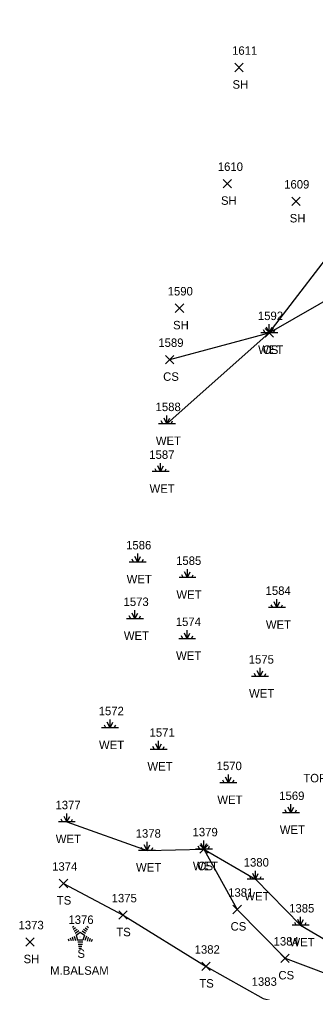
# Model space of a CAD drawing. Extents: x 1554917 to 1555870, y 813367 to 816333.
# Drawn here: x 1555068.3 to 1555138.3, y 813931.9 to 814161.6 of the extents above; entities that cross this region are included whole.
import ezdxf

# ---------------------------------------------------------------- set-up
doc = ezdxf.new("R2010")
doc.units = 0
for name, color, linetype in [('L_A', 7, 'Continuous'), ('L_C', 7, 'Continuous'), ('L_I', 7, 'Continuous'), ('L_TIC', 7, 'Continuous'), ('LELB', 7, 'Continuous'), ('LTC', 7, 'Continuous'), ('LWET', 7, 'Continuous'), ('U_C', 7, 'Continuous')]:
    doc.layers.add(name, color=color, linetype=linetype)

msp = doc.modelspace()

# ---------------------------------------------------------------- linework, layer by layer
at = {"layer": 'L_TIC'}
for points in [[(1555119.17, 814149.25), (1555121.17, 814151.25)], [(1555121.17, 814149.25), (1555119.17, 814151.25)], [(1555116.44, 814121.84), (1555118.44, 814123.84)], [(1555118.44, 814121.84), (1555116.44, 814123.84)], [(1555132.68, 814117.68), (1555134.68, 814119.68)], [(1555134.68, 814117.68), (1555132.68, 814119.68)], [(1555105.12, 814092.44), (1555107.12, 814094.44)], [(1555107.12, 814092.44), (1555105.12, 814094.44)], [(1555126.34, 814086.63), (1555128.34, 814088.63)], [(1555128.34, 814086.63), (1555126.34, 814088.63)], [(1555102.83, 814080.29), (1555104.83, 814082.29)], [(1555104.83, 814080.29), (1555102.83, 814082.29)], [(1555110.92, 813964.76), (1555112.92, 813966.76)], [(1555112.92, 813964.76), (1555110.92, 813966.76)], [(1555077.74, 813956.64), (1555079.74, 813958.64)], [(1555079.74, 813956.64), (1555077.74, 813958.64)], [(1555118.76, 813950.5), (1555120.76, 813952.5)], [(1555120.76, 813950.5), (1555118.76, 813952.5)], [(1555091.79, 813949.17), (1555093.79, 813951.17)], [(1555093.79, 813949.17), (1555091.79, 813951.17)], [(1555069.81, 813942.81), (1555071.81, 813944.81)], [(1555071.81, 813942.81), (1555069.81, 813944.81)], [(1555130.06, 813938.98), (1555132.06, 813940.98)], [(1555132.06, 813938.98), (1555130.06, 813940.98)], [(1555111.4, 813937.05), (1555113.4, 813939.05)], [(1555113.4, 813937.05), (1555111.4, 813939.05)]]:
    msp.add_lwpolyline(points, dxfattribs=at)
at = {"layer": 'LELB'}
for points in [[(1555103.83, 814081.29), (1555127.34, 814087.63), (1555145.8, 814111.67), (1555155.27, 814142.44), (1555178.24, 814154.02), (1555199.22, 814158.86), (1555221.17, 814170.73)], [(1555111.92, 813965.76), (1555119.76, 813951.5), (1555131.06, 813939.98), (1555141.33, 813936.14), (1555158.29, 813940)], [(1555078.74, 813957.64), (1555092.79, 813950.17), (1555112.4, 813938.05), (1555125.87, 813930.47), (1555142.24, 813926.36), (1555153.95, 813930.09)]]:
    msp.add_lwpolyline(points, dxfattribs=at)
at = {"layer": 'LTC'}
for p, q in [((1555080.83, 813947.29), (1555081.18, 813947.55)), ((1555081.04, 813946.83), (1555081.57, 813947.21)), ((1555081.25, 813946.36), (1555081.95, 813946.87)), ((1555081.46, 813945.89), (1555082.34, 813946.53)), ((1555081.68, 813945.44), (1555082.69, 813946.17)), ((1555081.68, 813945.44), (1555082.07, 813944.25)), ((1555082.69, 813946.17), (1555083.69, 813945.45)), ((1555083.11, 813946.49), (1555083.92, 813945.9)), ((1555083.69, 813945.45), (1555083.3, 813944.25)), ((1555083.49, 813946.83), (1555084.16, 813946.34)), ((1555083.86, 813947.18), (1555084.41, 813946.78)), ((1555084.23, 813947.53), (1555084.65, 813947.23)), ((1555079.86, 813944.57), (1555080.01, 813944.1)), ((1555080.32, 813944.79), (1555080.53, 813944.14)), ((1555080.77, 813945), (1555081.04, 813944.17)), ((1555081.23, 813945.22), (1555081.56, 813944.2)), ((1555083.3, 813944.25), (1555082.07, 813944.25)), ((1555083.26, 813943.75), (1555082.12, 813943.75)), ((1555083.18, 813943.25), (1555082.19, 813943.25)), ((1555084.13, 813945.18), (1555083.79, 813944.14)), ((1555084.57, 813944.93), (1555084.29, 813944.04)), ((1555085.02, 813944.68), (1555084.78, 813943.95)), ((1555085.46, 813944.43), (1555085.28, 813943.85)), ((1555083.09, 813942.75), (1555082.26, 813942.75)), ((1555083.01, 813942.25), (1555082.34, 813942.25))]:
    msp.add_line(p, q, dxfattribs=at)
at = {"layer": 'LWET'}
for p, q in [((1555126.34, 814087.63), (1555126.01, 814088.3)), ((1555127.34, 814087.63), (1555126.67, 814088.97)), ((1555127.34, 814087.63), (1555127.34, 814089.63)), ((1555127.34, 814087.63), (1555128.01, 814088.97)), ((1555128.34, 814087.63), (1555128.67, 814088.3)), ((1555129.34, 814087.63), (1555125.34, 814087.63)), ((1555103.17, 814066.14), (1555102.51, 814067.48)), ((1555103.17, 814066.14), (1555103.17, 814068.14)), ((1555103.17, 814066.14), (1555103.84, 814067.48)), ((1555105.17, 814066.14), (1555101.17, 814066.14)), ((1555102.17, 814066.14), (1555101.84, 814066.81)), ((1555104.17, 814066.14), (1555104.51, 814066.81)), ((1555101.68, 814054.86), (1555101.02, 814056.2)), ((1555101.68, 814054.86), (1555101.68, 814056.86)), ((1555101.68, 814054.86), (1555102.35, 814056.2)), ((1555103.68, 814054.86), (1555099.68, 814054.86)), ((1555100.68, 814054.86), (1555100.35, 814055.53)), ((1555102.68, 814054.86), (1555103.02, 814055.53)), ((1555096.27, 814033.49), (1555096.27, 814035.49)), ((1555098.27, 814033.49), (1555094.27, 814033.49)), ((1555095.27, 814033.49), (1555094.94, 814034.16)), ((1555096.27, 814033.49), (1555095.61, 814034.82)), ((1555096.27, 814033.49), (1555096.94, 814034.82)), ((1555097.27, 814033.49), (1555097.61, 814034.16)), ((1555107.02, 814029.83), (1555106.69, 814030.5)), ((1555108.02, 814029.83), (1555107.35, 814031.16)), ((1555108.02, 814029.83), (1555108.02, 814031.83)), ((1555108.02, 814029.83), (1555108.69, 814031.16)), ((1555109.02, 814029.83), (1555109.35, 814030.5)), ((1555110.02, 814029.83), (1555106.02, 814029.83)), ((1555129.16, 814022.75), (1555128.5, 814024.08)), ((1555129.16, 814022.75), (1555129.16, 814024.75)), ((1555129.16, 814022.75), (1555129.83, 814024.08)), ((1555095.61, 814020.13), (1555094.94, 814021.47)), ((1555095.61, 814020.13), (1555095.61, 814022.13)), ((1555095.61, 814020.13), (1555096.27, 814021.47)), ((1555131.16, 814022.75), (1555127.16, 814022.75)), ((1555128.16, 814022.75), (1555127.83, 814023.42)), ((1555130.16, 814022.75), (1555130.5, 814023.42)), ((1555097.61, 814020.13), (1555093.61, 814020.13)), ((1555094.61, 814020.13), (1555094.27, 814020.8)), ((1555096.61, 814020.13), (1555096.94, 814020.8)), ((1555107.95, 814015.41), (1555107.28, 814016.75)), ((1555107.95, 814015.41), (1555107.95, 814017.41)), ((1555107.95, 814015.41), (1555108.61, 814016.75)), ((1555109.95, 814015.41), (1555105.95, 814015.41)), ((1555106.95, 814015.41), (1555106.61, 814016.08)), ((1555108.95, 814015.41), (1555109.28, 814016.08)), ((1555125.18, 814006.52), (1555124.52, 814007.86)), ((1555125.18, 814006.52), (1555125.18, 814008.52)), ((1555125.18, 814006.52), (1555125.85, 814007.86)), ((1555127.18, 814006.52), (1555123.18, 814006.52)), ((1555124.18, 814006.52), (1555123.85, 814007.19)), ((1555126.18, 814006.52), (1555126.52, 814007.19)), ((1555089.73, 813994.35), (1555089.73, 813996.35)), ((1555091.73, 813994.35), (1555087.73, 813994.35)), ((1555088.73, 813994.35), (1555088.4, 813995.02)), ((1555089.73, 813994.35), (1555089.07, 813995.69)), ((1555089.73, 813994.35), (1555090.4, 813995.69)), ((1555090.73, 813994.35), (1555091.07, 813995.02)), ((1555103.19, 813989.27), (1555099.19, 813989.27)), ((1555100.19, 813989.27), (1555099.85, 813989.93)), ((1555101.19, 813989.27), (1555100.52, 813990.6)), ((1555101.19, 813989.27), (1555101.19, 813991.27)), ((1555101.19, 813989.27), (1555101.85, 813990.6)), ((1555102.19, 813989.27), (1555102.52, 813989.93)), ((1555117.69, 813981.39), (1555117.02, 813982.72)), ((1555117.69, 813981.39), (1555117.69, 813983.39)), ((1555117.69, 813981.39), (1555118.35, 813982.72)), ((1555119.69, 813981.39), (1555115.69, 813981.39)), ((1555116.69, 813981.39), (1555116.35, 813982.05)), ((1555118.69, 813981.39), (1555119.02, 813982.05)), ((1555132.45, 813974.33), (1555131.78, 813975.66)), ((1555132.45, 813974.33), (1555132.45, 813976.33)), ((1555132.45, 813974.33), (1555133.12, 813975.66)), ((1555079.52, 813972.15), (1555078.86, 813973.48)), ((1555079.52, 813972.15), (1555079.52, 813974.15)), ((1555079.52, 813972.15), (1555080.19, 813973.48)), ((1555134.45, 813974.33), (1555130.45, 813974.33)), ((1555131.45, 813974.33), (1555131.12, 813974.99)), ((1555133.45, 813974.33), (1555133.78, 813974.99)), ((1555081.52, 813972.15), (1555077.52, 813972.15)), ((1555078.52, 813972.15), (1555078.19, 813972.81)), ((1555080.52, 813972.15), (1555080.86, 813972.81)), ((1555097.48, 813965.44), (1555097.14, 813966.11)), ((1555098.48, 813965.44), (1555097.81, 813966.78)), ((1555098.48, 813965.44), (1555098.48, 813967.44)), ((1555098.48, 813965.44), (1555099.14, 813966.78)), ((1555099.48, 813965.44), (1555099.81, 813966.11)), ((1555110.92, 813965.76), (1555110.58, 813966.43)), ((1555111.92, 813965.76), (1555111.25, 813967.09)), ((1555111.92, 813965.76), (1555111.92, 813967.76)), ((1555111.92, 813965.76), (1555112.58, 813967.09)), ((1555112.92, 813965.76), (1555113.25, 813966.43)), ((1555100.48, 813965.44), (1555096.48, 813965.44)), ((1555113.92, 813965.76), (1555109.92, 813965.76)), ((1555123.09, 813958.62), (1555122.75, 813959.29)), ((1555124.09, 813958.62), (1555123.42, 813959.96)), ((1555124.09, 813958.62), (1555124.09, 813960.62)), ((1555124.09, 813958.62), (1555124.75, 813959.96)), ((1555125.09, 813958.62), (1555125.42, 813959.29)), ((1555126.09, 813958.62), (1555122.09, 813958.62)), ((1555136.73, 813947.78), (1555132.73, 813947.78)), ((1555133.73, 813947.78), (1555133.4, 813948.45)), ((1555134.73, 813947.78), (1555134.06, 813949.11)), ((1555134.73, 813947.78), (1555134.73, 813949.78)), ((1555134.73, 813947.78), (1555135.4, 813949.11)), ((1555135.73, 813947.78), (1555136.06, 813948.45))]:
    msp.add_line(p, q, dxfattribs=at)
for points in [[(1555103.17, 814066.14), (1555127.34, 814087.63), (1555156.87, 814104.54), (1555167.03, 814135.02), (1555182.39, 814142.18), (1555199.42, 814142.56), (1555215.8, 814144.46), (1555225.01, 814142.8)], [(1555079.52, 813972.15), (1555098.48, 813965.44), (1555111.92, 813965.76), (1555124.09, 813958.62), (1555134.73, 813947.78), (1555144.25, 813942.2), (1555154.27, 813942.5), (1555154.52, 813966.83), (1555160.01, 813989.73), (1555171.92, 814009.61), (1555193.51, 814053.28), (1555197.92, 814059.14), (1555201.96, 814084.83), (1555215.92, 814112.52), (1555222.38, 814128.7), (1555225.01, 814142.8)]]:
    msp.add_lwpolyline(points, dxfattribs=at)

# ---------------------------------------------------------------- texts
at = {"layer": 'L_A'}
for s, p in [('SH', (1555118.66, 814145.25)), ('SH', (1555115.93, 814117.84)), ('SH', (1555132.17, 814113.68)), ('SH', (1555104.61, 814088.44)), ('WET', (1555124.72, 814082.63)), ('CS', (1555125.78, 814082.63)), ('CS', (1555102.27, 814076.29)), ('WET', (1555100.55, 814061.14)), ('WET', (1555099.06, 814049.86)), ('WET', (1555093.65, 814028.49)), ('WET', (1555105.4, 814024.83)), ('WET', (1555126.54, 814017.75)), ('WET', (1555092.99, 814015.13)), ('WET', (1555105.32, 814010.41)), ('WET', (1555122.56, 814001.52)), ('WET', (1555087.11, 813989.35)), ('WET', (1555098.56, 813984.27)), ('WET', (1555115.07, 813976.39)), ('WET', (1555129.83, 813969.33)), ('WET', (1555076.9, 813967.15)), ('WET', (1555095.86, 813960.44)), ('WET', (1555109.3, 813960.76)), ('CS', (1555110.36, 813960.76)), ('TS', (1555077.15, 813952.64)), ('WET', (1555121.46, 813953.62)), ('CS', (1555118.2, 813946.5)), ('TS', (1555091.2, 813945.17)), ('WET', (1555132.11, 813942.78)), ('SH', (1555069.29, 813938.81)), ('S', (1555082.02, 813940.08)), ('CS', (1555129.5, 813934.98)), ('TS', (1555110.81, 813933.05))]:
    msp.add_text(s, height=2, dxfattribs=at).set_placement(p)
at = {"layer": 'L_C'}
msp.add_text('M.BALSAM', height=2, dxfattribs=at).set_placement((1555075.59, 813936.08))
at = {"layer": 'L_I'}
for s, p in [('1611', (1555118.56, 814153.25)), ('1610', (1555115.18, 814125.84)), ('1609', (1555130.86, 814121.68)), ('1590', (1555103.34, 814096.44)), ('1592', (1555124.65, 814090.63)), ('1592', (1555124.65, 814090.63)), ('1589', (1555101.13, 814084.29)), ('1588', (1555100.48, 814069.14)), ('1587', (1555098.99, 814057.86)), ('1586', (1555093.52, 814036.49)), ('1585', (1555105.33, 814032.83)), ('1584', (1555126.47, 814025.75)), ('1573', (1555092.91, 814023.13)), ('1574', (1555105.25, 814018.41)), ('1575', (1555122.49, 814009.52)), ('1572', (1555087.04, 813997.35)), ('1571', (1555099.06, 813992.27)), ('1570', (1555114.91, 813984.39)), ('1569', (1555129.7, 813977.33)), ('1377', (1555076.83, 813975.15)), ('1379', (1555109.22, 813968.76)), ('1379', (1555109.22, 813968.76)), ('1378', (1555095.78, 813968.44)), ('1374', (1555076.04, 813960.64)), ('1380', (1555121.31, 813961.62)), ('1375', (1555090.1, 813953.17)), ('1381', (1555117.63, 813954.5)), ('1385', (1555132.04, 813950.78)), ('1376', (1555079.89, 813948.08)), ('1373', (1555068.11, 813946.81)), ('1384', (1555128.37, 813942.98)), ('1382', (1555109.71, 813941.05)), ('1383', (1555123.18, 813933.47))]:
    msp.add_text(s, height=2, dxfattribs=at).set_placement(p)
at = {"layer": 'LTC'}
msp.add_text('.', height=1.04, rotation=270, dxfattribs=at).set_placement((1555082.58, 813945.19))
at = {"layer": 'U_C'}
msp.add_text('TOP CAP MONITORING WELL', height=2, dxfattribs=at).set_placement((1555135.38, 813981.5))

doc.saveas('drawing.dxf')
